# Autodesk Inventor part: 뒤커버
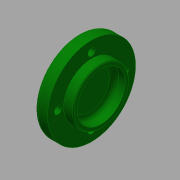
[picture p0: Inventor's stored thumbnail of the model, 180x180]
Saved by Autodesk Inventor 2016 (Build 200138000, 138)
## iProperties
Created: 2015-12
Part Number: 뒤커버
Material: 알루미늄 6061
Document SubType Name: Modeling
Designer: mduedu
Density: 2.71 g/cm^3
Appearance: 진녹색
Author: mduedu
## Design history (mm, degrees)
sketch "스케치1"
  geometry: L1 (0, 0)-(14, 0); L2 (14, 0)-(14, 17.5); L3 (14, 17.5)-(8, 17.5); L4 (8, 17.5)-(8, 27.5); L5 (8, 27.5)-(0, 27.5); L6 (0, 27.5)-(0, 0)
  constraints: 12 end point, 4 parallel, 1 horizontal, 1 perpendicular
  dimensions: "d0" = 14 distance between parallel lines of L2 L6; "d2" = 8 distance of L4.end L5.end; "d3" = 55 diameter of L5 L1; "d4" = 35 diameter of L3 L1
revolve "회전1" sketch "스케치1" stored, may be unused: angle "d5" = 90 deg
hole "구멍1" diameter "d8" = 30; stored, may be unused: countersink angle "d12" = 90 deg, drill point angle "d14" = 0 deg; dims "d9" = 6, "d10" = 4, "d11" = 2, "d13" = 7, "d39" = 10, "d40" = 10
fillet "모깎기3" dims "d38" = 2
fillet "모깎기4" dims "d41" = 3
chamfer "모따기2" distance "d42" = 0.5; stored, may be unused: second distance "d43" = 2, angle "d44" = 45 deg
sketch "스케치2" dims "d45" = 42
  geometry: 6 further points
  constraints: 2 vertical alignment, 1 coincident, 7 other
  dimensions: "d48" = 360 deg dimension on point (0, 0) point (0, 21) (derived)
sketch "스케치3"
  geometry: 4 further points
hole "구멍4" sketch "스케치3" at (-21, 0), (0, -21), (21, 0), (0, 21) diameter "d50" = 4.5; stored, may be unused: countersink angle "d54" = 90 deg, drill point angle "d56" = 0 deg; dims "d51" = 6, "d52" = 8, "d53" = 4.6, "d55" = 8
node "솔리드1"
